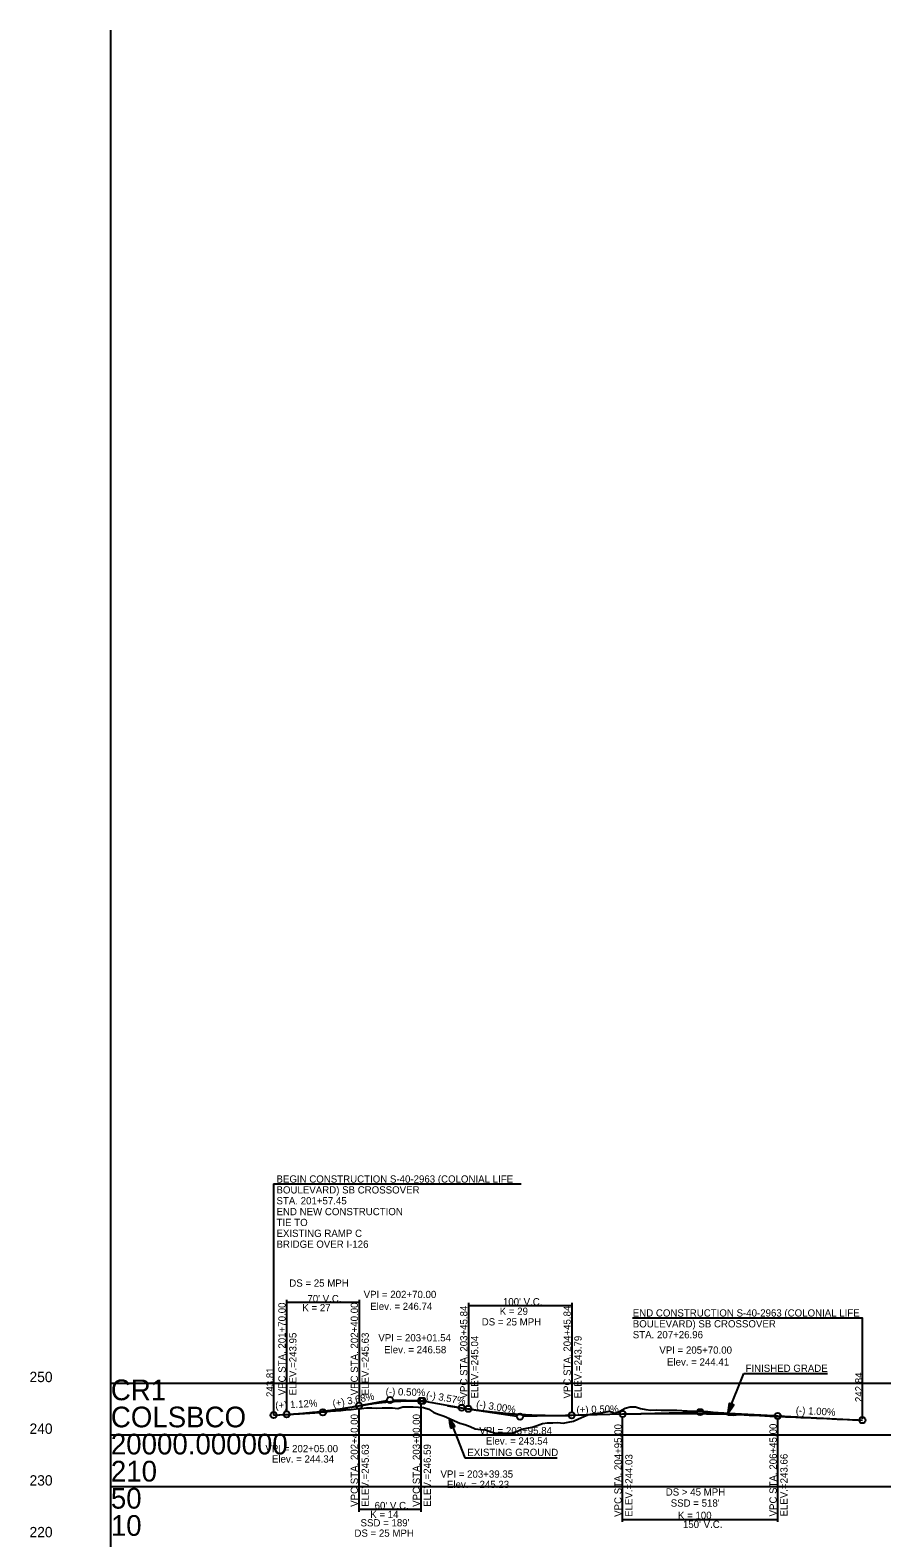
# Model space of a CAD drawing. Extents: x 69 to 2003113, y 512 to 837401.
# Drawn here: x 1923594 to 1924418, y 789713 to 791171 of the extents above; entities that cross this region are included whole.
import ezdxf

# ---------------------------------------------------------------- set-up
doc = ezdxf.new("R2010")
doc.units = 0
for name, color, linetype in [('BR_AUTO DIMENSION', 7, 'Continuous'), ('BR_BORDER LINES', 7, 'Continuous'), ('BR_CENTER LINE BASELINE', 7, 'Continuous'), ('BR_CONCRETE', 7, 'Continuous'), ('BR_GRID DOTS', 7, 'Continuous'), ('BR_GRID LINES', 7, 'Continuous'), ('BR_TEXT', 7, 'Continuous'), ('MISCELLANEOUS', 7, 'Continuous'), ('RD_PD_ALT1_TrvlWay', 7, 'Continuous'), ('RD_SHT_IplotShp', 7, 'Continuous')]:
    doc.layers.add(name, color=color, linetype=linetype)

msp = doc.modelspace()

# ---------------------------------------------------------------- linework, layer by layer
at = {"layer": 'BR_AUTO DIMENSION'}
for p, q in [((1923672.4, 788412.9), (1923672.4, 791171.1)), ((1923672.4, 789862.9), (1924834, 789862.9)), ((1923672.4, 789812.9), (1924834, 789812.9)), ((1923672.4, 789762.9), (1924834, 789762.9))]:
    msp.add_line(p, q, dxfattribs=at)
at = {"layer": 'BR_BORDER LINES'}
msp.add_line((1923672.4, 789662.9), (1923672.4, 790912.9), dxfattribs=at)
at = {"layer": 'BR_CENTER LINE BASELINE'}
for p, q in [((1923880.3, 789835.2), (1923939.4, 789846.1)), ((1923970.9, 789845.9), (1923945.4, 789846.5)), ((1923998, 789841.1), (1924065.2, 789831)), ((1923829.8, 789832.1), (1923874.4, 789834.5)), ((1924139.2, 789832.4), (1924071.2, 789830.7)), ((1924171.4, 789833.2), (1924239.4, 789834.9)), ((1924313.3, 789831.4), (1924245.4, 789834.8))]:
    msp.add_line(p, q, dxfattribs=at)
for centre in [(1923942.4, 789846.6), (1923973.9, 789845.8), (1924011.7, 789839.1), (1923829.8, 789832), (1923877.4, 789834.6), (1924068.2, 789830.6), (1924242.4, 789834.9), (1924399.3, 789827.1)]:
    msp.add_circle(centre, 3, dxfattribs=at)
at = {"layer": 'BR_GRID DOTS'}
for p, q in [((1923829.8, 790055.6), (1923829.8, 789832)), ((1923842.4, 789943.6), (1923842.4, 789835.7)), ((1923912.4, 789943.6), (1923912.4, 789844.1)), ((1923842.4, 789941.1), (1923912.4, 789941.1)), ((1924018.2, 789940.6), (1924018.2, 789841.1)), ((1924018.2, 789938.1), (1924118.2, 789938.1)), ((1924118.2, 789940.6), (1924118.2, 789834.8)), ((1923972.4, 789738.6), (1923972.4, 789842.8)), ((1923912.4, 789738.6), (1923912.4, 789838.1)), ((1924167.4, 789728.7), (1924167.4, 789830.1)), ((1924317.4, 789728.7), (1924317.4, 789828.2)), ((1923912.4, 789741.1), (1923972.4, 789741.1)), ((1924167.4, 789731.2), (1924317.4, 789731.2))]:
    msp.add_line(p, q, dxfattribs=at)
for points in [[(1923829.8, 790055.6), (1924069.4, 790055.6)], [(1924399.3, 789828.4), (1924399.3, 789925.7), (1924176.8, 789925.7)]]:
    msp.add_lwpolyline(points, dxfattribs=at)
for centre in [(1923912.4, 789841.1), (1923972.4, 789845.8), (1923842.4, 789832.7), (1924018.2, 789838.1), (1924118.2, 789831.8), (1924167.4, 789833.1), (1924317.4, 789831.2)]:
    msp.add_circle(centre, 3, dxfattribs=at)
at = {"layer": 'BR_GRID LINES'}
for p, q in [((1923972.4, 789845.8), (1923973.9, 789845.8)), ((1923973.9, 789845.8), (1924011.7, 789839.1)), ((1923829.8, 789832), (1923842.4, 789832.7)), ((1924011.7, 789839.1), (1924018.2, 789838.1)), ((1924118.2, 789831.8), (1924167.4, 789833.1)), ((1924317.4, 789831.2), (1924399.3, 789827.1))]:
    msp.add_line(p, q, dxfattribs=at)
for points in [[(1923912.4, 789841.1), (1923913.6, 789841.3), (1923914.8, 789841.5), (1923916, 789841.7), (1923917.2, 789841.9), (1923918.4, 789842.1), (1923919.6, 789842.3), (1923920.8, 789842.5), (1923922, 789842.7), (1923923.2, 789842.9), (1923924.4, 789843), (1923925.6, 789843.2), (1923926.8, 789843.4), (1923928, 789843.5), (1923929.2, 789843.7), (1923930.4, 789843.8), (1923931.6, 789844), (1923932.8, 789844.1), (1923934, 789844.2), (1923935.2, 789844.4), (1923936.4, 789844.5), (1923937.6, 789844.6), (1923938.8, 789844.7), (1923940, 789844.8), (1923941.2, 789844.9), (1923942.4, 789845), (1923943.6, 789845.1), (1923944.8, 789845.2), (1923946, 789845.3), (1923947.2, 789845.4), (1923948.4, 789845.4), (1923949.6, 789845.5), (1923950.8, 789845.6), (1923952, 789845.6), (1923953.2, 789845.7), (1923954.4, 789845.7), (1923955.6, 789845.8), (1923956.8, 789845.8), (1923958, 789845.8), (1923959.2, 789845.9), (1923960.4, 789845.9), (1923961.6, 789845.9), (1923962.8, 789845.9), (1923964, 789845.9), (1923965.2, 789845.9), (1923966.4, 789845.9), (1923967.6, 789845.9), (1923968.8, 789845.9), (1923970, 789845.9), (1923971.2, 789845.9), (1923972.4, 789845.8)], [(1923842.4, 789832.7), (1923843.8, 789832.7), (1923845.2, 789832.8), (1923846.6, 789832.9), (1923848, 789833), (1923849.4, 789833.1), (1923850.8, 789833.2), (1923852.2, 789833.3), (1923853.6, 789833.4), (1923855, 789833.5), (1923856.4, 789833.6), (1923857.8, 789833.7), (1923859.2, 789833.9), (1923860.6, 789834), (1923862, 789834.1), (1923863.4, 789834.2), (1923864.8, 789834.4), (1923866.2, 789834.5), (1923867.6, 789834.7), (1923869, 789834.8), (1923870.4, 789834.9), (1923871.8, 789835.1), (1923873.2, 789835.3), (1923874.6, 789835.4), (1923876, 789835.6), (1923877.4, 789835.7), (1923878.8, 789835.9), (1923880.2, 789836.1), (1923881.6, 789836.3), (1923883, 789836.4), (1923884.4, 789836.6), (1923885.8, 789836.8), (1923887.2, 789837), (1923888.6, 789837.2), (1923890, 789837.4), (1923891.4, 789837.6), (1923892.8, 789837.8), (1923894.2, 789838), (1923895.6, 789838.2), (1923897, 789838.5), (1923898.4, 789838.7), (1923899.8, 789838.9), (1923901.2, 789839.1), (1923902.6, 789839.4), (1923904, 789839.6), (1923905.4, 789839.8), (1923906.8, 789840.1), (1923908.2, 789840.3), (1923909.6, 789840.6), (1923911, 789840.8), (1923912.4, 789841.1)], [(1924018.2, 789838.1), (1924020.2, 789837.8), (1924022.2, 789837.5), (1924024.2, 789837.2), (1924026.2, 789836.9), (1924028.2, 789836.7), (1924030.2, 789836.4), (1924032.2, 789836.2), (1924034.2, 789835.9), (1924036.2, 789835.7), (1924038.2, 789835.4), (1924040.2, 789835.2), (1924042.2, 789835), (1924044.2, 789834.8), (1924046.2, 789834.6), (1924048.2, 789834.4), (1924050.2, 789834.2), (1924052.2, 789834), (1924054.2, 789833.8), (1924056.2, 789833.6), (1924058.2, 789833.5), (1924060.2, 789833.3), (1924062.2, 789833.2), (1924064.2, 789833), (1924066.2, 789832.9), (1924068.2, 789832.8), (1924070.2, 789832.6), (1924072.2, 789832.5), (1924074.2, 789832.4), (1924076.2, 789832.3), (1924078.2, 789832.2), (1924080.2, 789832.1), (1924082.2, 789832.1), (1924084.2, 789832), (1924086.2, 789831.9), (1924088.2, 789831.9), (1924090.2, 789831.8), (1924092.2, 789831.8), (1924094.2, 789831.7), (1924096.2, 789831.7), (1924098.2, 789831.7), (1924100.2, 789831.7), (1924102.2, 789831.7), (1924104.2, 789831.7), (1924106.2, 789831.7), (1924108.2, 789831.7), (1924110.2, 789831.7), (1924112.2, 789831.7), (1924114.2, 789831.7), (1924116.2, 789831.8), (1924118.2, 789831.8)], [(1924167.4, 789833.1), (1924170.4, 789833.1), (1924173.4, 789833.2), (1924176.4, 789833.3), (1924179.4, 789833.3), (1924182.4, 789833.4), (1924185.4, 789833.4), (1924188.4, 789833.5), (1924191.4, 789833.5), (1924194.4, 789833.6), (1924197.4, 789833.6), (1924200.4, 789833.6), (1924203.4, 789833.6), (1924206.4, 789833.7), (1924209.4, 789833.7), (1924212.4, 789833.7), (1924215.4, 789833.7), (1924218.4, 789833.7), (1924221.4, 789833.7), (1924224.4, 789833.7), (1924227.4, 789833.7), (1924230.4, 789833.6), (1924233.4, 789833.6), (1924236.4, 789833.6), (1924239.4, 789833.6), (1924242.4, 789833.5), (1924245.4, 789833.5), (1924248.4, 789833.4), (1924251.4, 789833.4), (1924254.4, 789833.3), (1924257.4, 789833.3), (1924260.4, 789833.2), (1924263.4, 789833.2), (1924266.4, 789833.1), (1924269.4, 789833), (1924272.4, 789832.9), (1924275.4, 789832.8), (1924278.4, 789832.8), (1924281.4, 789832.7), (1924284.4, 789832.6), (1924287.4, 789832.5), (1924290.4, 789832.4), (1924293.4, 789832.2), (1924296.4, 789832.1), (1924299.4, 789832), (1924302.4, 789831.9), (1924305.4, 789831.7), (1924308.4, 789831.6), (1924311.4, 789831.5), (1924314.4, 789831.3), (1924317.4, 789831.2)]]:
    msp.add_spline(points, degree=3, dxfattribs=at)
at = {"layer": 'BR_TEXT'}
for points in [[(1923829.8, 789831.9), (1923834.8, 789832.2), (1923839.8, 789832.5), (1923844.8, 789832.8), (1923849.8, 789833.1), (1923854.8, 789833.3), (1923859.8, 789833.6), (1923864.8, 789834), (1923869.8, 789834.3), (1923874.8, 789834.8), (1923879.8, 789835.3), (1923884.8, 789835.7), (1923889.8, 789836.1), (1923894.8, 789836.5), (1923899.8, 789837), (1923904.8, 789837.5), (1923909.8, 789838), (1923914.8, 789838.5), (1923919.8, 789838.9), (1923924.8, 789839), (1923929.8, 789838.8), (1923934.8, 789838.9), (1923939.8, 789839), (1923944.8, 789838.9), (1923949.8, 789838.3), (1923954.8, 789840.1), (1923959.8, 789840), (1923964.8, 789839.9), (1923969.8, 789839.7), (1923974.8, 789839.5), (1923979.8, 789837.6), (1923984.8, 789834.6), (1923989.8, 789832.5), (1923994.8, 789830.9), (1923999.8, 789828.7), (1924004.8, 789826.5), (1924009.8, 789824.3), (1924014.8, 789822.8), (1924019.8, 789820.9), (1924024.8, 789818.9), (1924029.8, 789818.1), (1924034.8, 789817.8), (1924039.8, 789815.9), (1924044.8, 789814.6), (1924049.8, 789814.6), (1924054.8, 789814.5), (1924059.8, 789814.4), (1924064.8, 789816.3), (1924069.8, 789818.5), (1924074.8, 789819.4), (1924079.8, 789820.4), (1924084.8, 789822.1), (1924089.8, 789823.8), (1924094.8, 789824.6), (1924099.8, 789824.7), (1924104.8, 789824.8), (1924109.8, 789824.2), (1924114.8, 789825.1), (1924119.8, 789826.3), (1924124.8, 789828.4), (1924129.8, 789830.6), (1924134.8, 789832.7), (1924139.8, 789833.7), (1924144.8, 789834), (1924149.8, 789834.8), (1924154.8, 789835.7), (1924159.8, 789833.8), (1924164.8, 789835.7), (1924169.8, 789838.8), (1924174.8, 789840.1), (1924179.8, 789839.9), (1924184.8, 789838.4), (1924189.8, 789837.5), (1924194.8, 789836.9), (1924199.8, 789837.1), (1924204.8, 789836.9), (1924209.8, 789836.8), (1924214.8, 789836.8), (1924219.8, 789836.7), (1924224.8, 789836.4), (1924229.8, 789836), (1924234.8, 789835.8), (1924239.8, 789835.7), (1924244.8, 789835.8), (1924249.8, 789835.4), (1924254.8, 789835), (1924259.8, 789834.5), (1924264.8, 789834.3), (1924269.8, 789832.3), (1924274.8, 789832.1), (1924279.8, 789832.5), (1924284.8, 789832.3), (1924289.8, 789832.1), (1924294.8, 789831.8), (1924299.8, 789831.5), (1924304.8, 789831.2), (1924309.8, 789831), (1924314.8, 789830.8), (1924319.8, 789830.6), (1924324.8, 789830.4), (1924329.8, 789830.3)], [(1924329.8, 789830.3), (1924334.8, 789830), (1924339.8, 789829.8), (1924344.8, 789829.6), (1924349.8, 789829.3), (1924354.8, 789829.1), (1924359.8, 789828.9), (1924364.8, 789828.7), (1924369.8, 789828.4), (1924374.8, 789828.2), (1924379.8, 789828), (1924384.8, 789827.8), (1924389.8, 789827.5), (1924394.8, 789827.3), (1924399.3, 789827.1)]]:
    msp.add_lwpolyline(points, dxfattribs=at)
at = {"layer": 'RD_PD_ALT1_TrvlWay'}
for p, q in [((1924269.6, 789834.4), (1924284.6, 789872.3)), ((1924284.6, 789872.3), (1924365.4, 789872.3)), ((1924269.6, 789834.4), (1924270.9, 789843.6)), ((1924269.6, 789834.4), (1924270.9, 789843.6)), ((1924272.9, 789842.7), (1924269.6, 789834.4)), ((1924272.9, 789842.7), (1924269.6, 789834.4)), ((1924269.6, 789834.4), (1924275, 789841.9)), ((1924269.6, 789834.4), (1924275, 789841.9)), ((1924270.9, 789843.6), (1924275, 789841.9)), ((1924270.9, 789843.6), (1924275, 789841.9)), ((1923999.8, 789828.7), (1924014.8, 789790.7)), ((1924003.1, 789820.3), (1923999.8, 789828.7)), ((1923999.8, 789828.7), (1924005.2, 789821.1)), ((1923999.8, 789828.7), (1924001, 789819.5)), ((1924001, 789819.5), (1924005.2, 789821.1)), ((1924014.8, 789790.7), (1924104, 789790.7))]:
    msp.add_line(p, q, dxfattribs=at)
for points in [[(1924272.8, 789842.7), (1924269.8, 789834.9), (1924272.8, 789842.7), (1924269.8, 789835.3), (1924272.7, 789842.7), (1924269.9, 789835.5), (1924272.6, 789842.8), (1924269.9, 789835.9), (1924272.5, 789842.8), (1924270, 789836.4), (1924272.4, 789842.9), (1924270.1, 789836.9), (1924272.3, 789842.9), (1924270.1, 789837.3), (1924272.2, 789842.9), (1924270.2, 789837.7), (1924272.1, 789842.9), (1924270.2, 789838.1), (1924272, 789843), (1924270.3, 789838.5), (1924271.9, 789843), (1924270.3, 789839), (1924271.8, 789843.1), (1924270.4, 789839.6), (1924271.7, 789843.2), (1924270.4, 789840), (1924271.6, 789843.2), (1924270.5, 789840.6), (1924271.5, 789843.2), (1924270.6, 789841.1), (1924271.4, 789843.3), (1924270.7, 789841.6), (1924271.3, 789843.3), (1924270.7, 789842), (1924271.2, 789843.4), (1924270.8, 789842.5), (1924271.1, 789843.4), (1924270.9, 789843), (1924271, 789843.4)], [(1924272.8, 789842.7), (1924269.8, 789834.9), (1924272.8, 789842.7), (1924269.8, 789835.3), (1924272.7, 789842.7), (1924269.9, 789835.5), (1924272.6, 789842.8), (1924269.9, 789835.9), (1924272.5, 789842.8), (1924270, 789836.4), (1924272.4, 789842.9), (1924270.1, 789836.9), (1924272.3, 789842.9), (1924270.1, 789837.3), (1924272.2, 789842.9), (1924270.2, 789837.7), (1924272.1, 789842.9), (1924270.2, 789838.1), (1924272, 789843), (1924270.3, 789838.5), (1924271.9, 789843), (1924270.3, 789839), (1924271.8, 789843.1), (1924270.4, 789839.6), (1924271.7, 789843.2), (1924270.4, 789840), (1924271.6, 789843.2), (1924270.5, 789840.6), (1924271.5, 789843.2), (1924270.6, 789841.1), (1924271.4, 789843.3), (1924270.7, 789841.6), (1924271.3, 789843.3), (1924270.7, 789842), (1924271.2, 789843.4), (1924270.8, 789842.5), (1924271.1, 789843.4), (1924270.9, 789843), (1924271, 789843.4)], [(1924269.9, 789834.9), (1924273, 789842.6), (1924270.1, 789835.2), (1924273.1, 789842.6), (1924270.2, 789835.4), (1924273.2, 789842.6), (1924270.4, 789835.6), (1924273.2, 789842.5), (1924270.6, 789835.9), (1924273.3, 789842.5), (1924270.8, 789836.1), (1924273.4, 789842.5), (1924271, 789836.4), (1924273.5, 789842.5), (1924271.3, 789836.8), (1924273.6, 789842.4), (1924271.5, 789837.1), (1924273.7, 789842.4), (1924271.7, 789837.4), (1924273.7, 789842.4), (1924271.9, 789837.7), (1924273.8, 789842.3), (1924272.2, 789838.1), (1924273.9, 789842.3), (1924272.5, 789838.5), (1924274, 789842.3), (1924272.7, 789838.8), (1924274.1, 789842.3), (1924273, 789839.2), (1924274.1, 789842.2), (1924273.3, 789839.6), (1924274.2, 789842.1), (1924273.5, 789839.9), (1924274.3, 789842), (1924273.7, 789840.2), (1924274.4, 789842), (1924274, 789840.7), (1924274.5, 789842), (1924274.2, 789840.9), (1924274.7, 789842), (1924274.4, 789841.1), (1924274.8, 789841.8), (1924274.9, 789841.9), (1924274.7, 789841.9)], [(1924269.9, 789834.9), (1924273, 789842.6), (1924270.1, 789835.2), (1924273.1, 789842.6), (1924270.2, 789835.4), (1924273.2, 789842.6), (1924270.4, 789835.6), (1924273.2, 789842.5), (1924270.6, 789835.9), (1924273.3, 789842.5), (1924270.8, 789836.1), (1924273.4, 789842.5), (1924271, 789836.4), (1924273.5, 789842.5), (1924271.3, 789836.8), (1924273.6, 789842.4), (1924271.5, 789837.1), (1924273.7, 789842.4), (1924271.7, 789837.4), (1924273.7, 789842.4), (1924271.9, 789837.7), (1924273.8, 789842.3), (1924272.2, 789838.1), (1924273.9, 789842.3), (1924272.5, 789838.5), (1924274, 789842.3), (1924272.7, 789838.8), (1924274.1, 789842.3), (1924273, 789839.2), (1924274.1, 789842.2), (1924273.3, 789839.6), (1924274.2, 789842.1), (1924273.5, 789839.9), (1924274.3, 789842), (1924273.7, 789840.2), (1924274.4, 789842), (1924274, 789840.7), (1924274.5, 789842), (1924274.2, 789840.9), (1924274.7, 789842), (1924274.4, 789841.1), (1924274.8, 789841.8), (1924274.9, 789841.9), (1924274.7, 789841.9)], [(1924003, 789820.4), (1923999.9, 789828.2), (1924003, 789820.3), (1924000, 789827.8), (1924002.9, 789820.3), (1924000, 789827.5), (1924002.8, 789820.3), (1924000.1, 789827.2), (1924002.7, 789820.3), (1924000.1, 789826.7), (1924002.6, 789820.2), (1924000.2, 789826.2), (1924002.5, 789820.2), (1924000.3, 789825.8), (1924002.4, 789820.1), (1924000.4, 789825.3), (1924002.3, 789820.1), (1924000.4, 789824.9), (1924002.2, 789820), (1924000.4, 789824.6), (1924002.1, 789820), (1924000.5, 789824.1), (1924002, 789820), (1924000.6, 789823.5), (1924001.9, 789819.9), (1924000.6, 789823.1), (1924001.8, 789819.9), (1924000.7, 789822.5), (1924001.7, 789819.9), (1924000.8, 789822), (1924001.6, 789819.8), (1924000.9, 789821.5), (1924001.5, 789819.8), (1924000.9, 789821.1), (1924001.4, 789819.7), (1924001, 789820.6), (1924001.3, 789819.7), (1924001, 789820.1), (1924001.1, 789819.7)], [(1924000.1, 789828.2), (1924003.1, 789820.4), (1924000.3, 789827.9), (1924003.2, 789820.5), (1924000.4, 789827.7), (1924003.3, 789820.5), (1924000.6, 789827.5), (1924003.4, 789820.5), (1924000.8, 789827.2), (1924003.5, 789820.5), (1924001, 789827), (1924003.6, 789820.6), (1924001.2, 789826.7), (1924003.6, 789820.6), (1924001.4, 789826.3), (1924003.8, 789820.7), (1924001.6, 789826), (1924003.8, 789820.6), (1924001.9, 789825.7), (1924003.9, 789820.7), (1924002.1, 789825.3), (1924004, 789820.7), (1924002.3, 789825), (1924004.1, 789820.8), (1924002.7, 789824.5), (1924004.2, 789820.8), (1924002.9, 789824.3), (1924004.2, 789820.8), (1924003.2, 789823.9), (1924004.3, 789820.9), (1924003.4, 789823.5), (1924004.4, 789820.9), (1924003.7, 789823.2), (1924004.5, 789821), (1924003.9, 789822.9), (1924004.6, 789821), (1924004.2, 789822.4), (1924004.7, 789821), (1924004.4, 789822.1), (1924004.8, 789821.1), (1924004.6, 789822), (1924005, 789821.2), (1924005.1, 789821.2), (1924004.9, 789821.2)]]:
    msp.add_lwpolyline(points, dxfattribs=at)

# ---------------------------------------------------------------- texts
at = {"layer": 'BR_BORDER LINES'}
for s, p in [('CR1', (1923672.4, 789846.4)), ('COLSBCO', (1923672.4, 789820.2)), ('20000.000000', (1923672.4, 789794)), ('210', (1923672.4, 789767.8)), ('50', (1923672.4, 789741.6)), ('10', (1923672.4, 789715.3))]:
    msp.add_text(s, height=20, dxfattribs=at).set_placement(p)
at = {"layer": 'BR_CENTER LINE BASELINE'}
for s, rotation, p in [('(-) 0.50%', 358.5679, (1923938.1, 789851.4)), ('(+) 1.12%', 3.213, (1923831.6, 789837.9)), ('(+) 3.68%', 10.4336, (1923887.5, 789839.6)), ('(-) 3.57%', 349.878, (1923976.9, 789848.6)), ('(-) 3.00%', 351.4687, (1924025.4, 789839.5)), ('(+) 0.50%', 1.4321, (1924122.8, 789833.7)), ('(-) 1.00%', 357.1355, (1924334.7, 789833.3))]:
    msp.add_text(s, height=7, rotation=rotation, dxfattribs=at).set_placement(p)
at = {"layer": 'BR_CONCRETE'}
for s, p in [('VPC STA. 201+70.00 ', (1923841.4, 789851.1)), ('VPC STA. 202+40.00 ', (1923911.4, 789851.1)), ('VPC STA. 203+45.84 ', (1924017.2, 789848.1)), ('VPC STA. 204+45.84 ', (1924117.2, 789848.1)), ('ELEV.=243.95', (1923851.9, 789851.1)), ('ELEV.=245.63', (1923921.9, 789851.1)), ('ELEV.=245.04', (1924027.7, 789848.1)), ('ELEV.=243.79', (1924127.7, 789848.1)), ('VPC STA. 202+40.00 ', (1923911.4, 789743.3)), ('VPC STA. 203+00.00 ', (1923971.4, 789743.3)), ('VPC STA. 204+95.00 ', (1924166.4, 789733.6)), ('VPC STA. 206+45.00 ', (1924316.4, 789734)), ('ELEV.=245.63', (1923921.9, 789743.3)), ('ELEV.=246.59', (1923981.9, 789743.3)), ('ELEV.=244.03', (1924176.9, 789733.6)), ('ELEV.=243.66', (1924326.9, 789734))]:
    msp.add_text(s, height=7, rotation=90, dxfattribs=at).set_placement(p)
at = {"layer": 'BR_GRID DOTS'}
for s, p in [('DS = 25 MPH', (1923845, 789956.2)), ("70' V.C.", (1923862.5, 789941.1)), ("100' V.C.", (1924051.6, 789938.1)), ('K = 27', (1923857.6, 789932.4)), ('K = 29', (1924048.5, 789929)), ('DS = 25 MPH', (1924031.1, 789918.7)), ('DS > 45 MPH', (1924209.1, 789754.2)), ('K = 14', (1923923.3, 789732.5)), ("60' V.C.", (1923927.5, 789741.1)), ("SSD = 518'", (1924213.9, 789743.5)), ("SSD = 189'", (1923913.9, 789724.4)), ('K = 100', (1924220.9, 789731.6)), ("150' V.C.", (1924225.7, 789722.9)), ('DS = 25 MPH', (1923908, 789714.4))]:
    msp.add_text(s, height=7, dxfattribs=at).set_placement(p)
at = {"layer": 'MISCELLANEOUS'}
for s, p in [('250', (1923593.7, 789863.9)), ('240', (1923593.7, 789813.9)), ('230', (1923593.7, 789763.9)), ('220', (1923593.7, 789713.9))]:
    msp.add_text(s, height=10, dxfattribs=at).set_placement(p)
at = {"layer": 'RD_PD_ALT1_TrvlWay'}
for s, p in [('FINISHED GRADE', (1924286.2, 789873.8)), ('EXISTING GROUND', (1924017.2, 789792.5))]:
    msp.add_text(s, height=7, dxfattribs=at).set_placement(p)
at = {"layer": 'RD_SHT_IplotShp'}
for s, p in [('BEGIN CONSTRUCTION S-40-2963 (COLONIAL LIFE ', (1923832.6, 790056.8)), ('BOULEVARD) SB CROSSOVER', (1923832.6, 790046.3)), ('STA. 201+57.45', (1923832.6, 790035.8)), ('END NEW CONSTRUCTION', (1923832.6, 790025.3)), ('TIE TO ', (1923832.6, 790014.8)), ('EXISTING RAMP C', (1923832.6, 790004.3)), ('BRIDGE OVER I-126', (1923832.6, 789993.8)), ('VPI = 202+70.00', (1923916.9, 789945.2)), ('Elev. = 246.74', (1923923.2, 789933.7)), ('END CONSTRUCTION S-40-2963 (COLONIAL LIFE ', (1924177.2, 789927.3)), ('BOULEVARD) SB CROSSOVER', (1924177.2, 789916.8)), ('VPI = 203+01.54', (1923931.1, 789903.3)), ('STA. 207+26.96', (1924177.2, 789906.3)), ('Elev. = 246.58', (1923936.7, 789891.8)), ('VPI = 205+70.00', (1924202.9, 789891.4)), ('Elev. = 244.41', (1924210.3, 789879.9)), ('VPI = 203+95.84', (1924028.8, 789813.5)), ('VPI = 202+05.00', (1923821.9, 789796.1)), ('Elev. = 243.54', (1924035.1, 789803.5)), ('Elev. = 244.34', (1923828.2, 789786.1)), ('VPI = 203+39.35', (1923991.2, 789771.5)), ('Elev. = 245.23', (1923997.5, 789761.5))]:
    msp.add_text(s, height=7, dxfattribs=at).set_placement(p)
for s, p in [('243.81', (1923829.8, 789849.5)), ('242.84', (1924399.3, 789844.6))]:
    msp.add_text(s, height=7, rotation=90, dxfattribs=at).set_placement(p)

doc.saveas('drawing.dxf')
